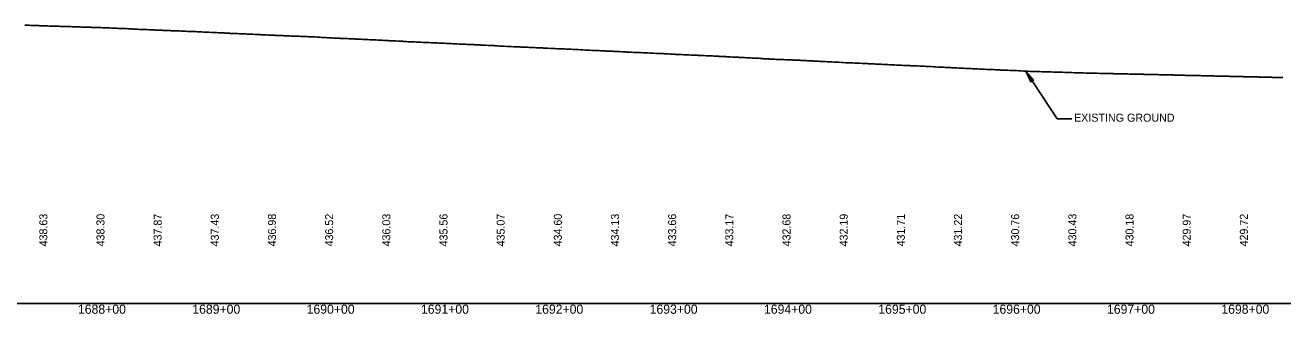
# Model space of a CAD drawing. Extents: x 2017200 to 2047700, y 854850 to 893350.
# Drawn here: x 2023730 to 2024830, y 856091 to 856344 of the extents above; entities that cross this region are included whole.
import ezdxf

# ---------------------------------------------------------------- set-up
doc = ezdxf.new("R2010")
doc.units = 0
for name, color, linetype in [('RD_DDB_Profile_EX', 7, 'Continuous'), ('RD_DDB_Profile_Lbl', 7, 'Continuous'), ('RD_DDB_StaTX', 7, 'Continuous'), ('RD_DDB_StripGrade', 7, 'Continuous'), ('RD_GPK_Profile_Cell', 7, 'Continuous')]:
    doc.layers.add(name, color=color, linetype=linetype)

msp = doc.modelspace()

# ---------------------------------------------------------------- linework, layer by layer
at = {"layer": 'RD_DDB_Profile_EX'}
msp.add_lwpolyline([(2023729.2, 856343.9), (2023729.6, 856343.9), (2023730.4, 856343.9), (2023731.1, 856343.8), (2023732.5, 856343.8), (2023733.1, 856343.8), (2023734.5, 856343.7), (2023735.1, 856343.7), (2023736.6, 856343.6), (2023737.1, 856343.6), (2023737.4, 856343.6), (2023738.7, 856343.6), (2023739, 856343.6), (2023740.7, 856343.5), (2023741.5, 856343.5), (2023742.4, 856343.4), (2023743.4, 856343.4), (2023744.5, 856343.4), (2023745.3, 856343.3), (2023746.7, 856343.3), (2023747.2, 856343.3), (2023748.7, 856343.2), (2023749.2, 856343.2), (2023750.8, 856343.1), (2023751.2, 856343.1), (2023753.2, 856343), (2023755.2, 856343), (2023756.9, 856342.9), (2023757.6, 856342.9), (2023758.7, 856342.9), (2023759.5, 856342.9), (2023760.8, 856342.8), (2023761.4, 856342.8), (2023762.9, 856342.8), (2023763.4, 856342.8), (2023764.9, 856342.7), (2023765.4, 856342.7), (2023767, 856342.6), (2023767.4, 856342.6), (2023768.6, 856342.6), (2023769, 856342.6), (2023769.4, 856342.6), (2023771, 856342.5), (2023772.2, 856342.4), (2023772.6, 856342.4), (2023773.9, 856342.4), (2023774.8, 856342.4), (2023775.8, 856342.3), (2023776.4, 856342.3), (2023776.9, 856342.3), (2023777.7, 856342.3), (2023779, 856342.2), (2023779.6, 856342.2), (2023781.1, 856342.2), (2023781.6, 856342.1), (2023783.1, 856342.1), (2023783.6, 856342.1), (2023784.2, 856342.1), (2023785.2, 856342), (2023785.5, 856342), (2023787.2, 856342), (2023787.5, 856341.9), (2023789.2, 856341.9), (2023790.1, 856341.8), (2023791, 856341.8), (2023792, 856341.8), (2023793.1, 856341.8), (2023793.8, 856341.7), (2023795.2, 856341.7), (2023795.8, 856341.7), (2023797.2, 856341.6), (2023797.7, 856341.6), (2023799.3, 856341.5), (2023799.8, 856341.5), (2023801.3, 856341.5), (2023801.7, 856341.4), (2023803.3, 856341.4), (2023805.1, 856341.3), (2023806.5, 856341.2), (2023807.2, 856341.2), (2023807.6, 856341.2), (2023808.3, 856341.2), (2023809.3, 856341.1), (2023810.2, 856341.1), (2023811.3, 856341), (2023812.1, 856341), (2023813.4, 856341), (2023814, 856340.9), (2023815.4, 856340.9), (2023816, 856340.8), (2023817.5, 856340.8), (2023818, 856340.8), (2023819.5, 856340.7), (2023819.9, 856340.7), (2023821.5, 856340.6), (2023822.8, 856340.6), (2023823.4, 856340.5), (2023824.5, 856340.5), (2023825.5, 856340.4), (2023826.4, 856340.4), (2023827.5, 856340.3), (2023828.3, 856340.3), (2023829.6, 856340.2), (2023830.2, 856340.2), (2023831, 856340.2), (2023831.6, 856340.2), (2023832.1, 856340.1), (2023833.6, 856340), (2023834.1, 856340), (2023835.7, 856340), (2023836.1, 856340), (2023837.7, 856339.9), (2023838.8, 856339.9), (2023839.6, 856339.8), (2023841, 856339.8), (2023841.7, 856339.7), (2023842.8, 856339.7), (2023843.7, 856339.6), (2023844.6, 856339.5), (2023845.7, 856339.5), (2023846.6, 856339.5), (2023847.8, 856339.4), (2023848.5, 856339.4), (2023849.8, 856339.4), (2023850.4, 856339.3), (2023851.8, 856339.3), (2023852.4, 856339.3), (2023853.8, 856339.2), (2023854.4, 856339.2), (2023855.8, 856339.1), (2023856.7, 856339.1), (2023857.5, 856339), (2023857.9, 856339), (2023859.2, 856339), (2023859.9, 856338.9), (2023861, 856338.9), (2023861.9, 856338.8), (2023862.2, 856338.8), (2023862.9, 856338.8), (2023863.9, 856338.8), (2023864.8, 856338.8), (2023866, 856338.7), (2023866.7, 856338.7), (2023868, 856338.6), (2023868.7, 856338.6), (2023870, 856338.5), (2023871.7, 856338.4), (2023872.1, 856338.4), (2023874.1, 856338.3), (2023874.8, 856338.3), (2023876.1, 856338.3), (2023876.4, 856338.3), (2023877.8, 856338.2), (2023878.1, 856338.2), (2023878.8, 856338.2), (2023880.1, 856338.1), (2023881.1, 856338.1), (2023882.2, 856338), (2023883.2, 856337.9), (2023884.2, 856337.9), (2023885.6, 856337.8), (2023886.2, 856337.8), (2023887.5, 856337.7), (2023888.2, 856337.7), (2023889.6, 856337.6), (2023890.2, 856337.6), (2023892.5, 856337.5), (2023893.4, 856337.5), (2023894.4, 856337.4), (2023894.7, 856337.4), (2023896.4, 856337.3), (2023897.1, 856337.3), (2023898.4, 856337.2), (2023899.4, 856337.2), (2023900.4, 856337.1), (2023901.2, 856337.1), (2023901.6, 856337.1), (2023902.4, 856337.1), (2023903.7, 856337), (2023904.4, 856336.9), (2023905.8, 856336.9), (2023906.4, 856336.9), (2023907.9, 856336.8), (2023908.4, 856336.8), (2023909, 856336.7), (2023909.9, 856336.7), (2023910.4, 856336.7), (2023912.8, 856336.6), (2023914.6, 856336.5), (2023915.3, 856336.5), (2023916.8, 856336.4), (2023917.5, 856336.4), (2023918.6, 856336.3), (2023919.7, 856336.3), (2023920.6, 856336.3), (2023921.8, 856336.2), (2023922.6, 856336.2), (2023923.9, 856336.1), (2023924.6, 856336.1), (2023926, 856336), (2023926.6, 856336), (2023928.1, 856335.9), (2023928.6, 856335.9), (2023930.9, 856335.8), (2023931.4, 856335.7), (2023932.4, 856335.7), (2023932.9, 856335.7), (2023933.3, 856335.6), (2023934.8, 856335.6), (2023935.6, 856335.5), (2023936.8, 856335.5), (2023937.8, 856335.4), (2023938.8, 856335.4), (2023940.2, 856335.3), (2023940.8, 856335.3), (2023942.1, 856335.2), (2023942.8, 856335.2), (2023944.2, 856335.1), (2023944.8, 856335.1), (2023946.2, 856335), (2023946.8, 856335), (2023948, 856335), (2023948.3, 856334.9), (2023948.8, 856334.9), (2023950.4, 856334.9), (2023951.2, 856334.9), (2023953.1, 856334.8), (2023953.7, 856334.7), (2023955.1, 856334.7), (2023955.9, 856334.6), (2023957, 856334.6), (2023958.1, 856334.5), (2023959, 856334.5), (2023960.2, 856334.4), (2023961, 856334.4), (2023962.3, 856334.3), (2023963, 856334.3), (2023963.6, 856334.3), (2023964.4, 856334.2), (2023965, 856334.2), (2023966.5, 856334.2), (2023967, 856334.1), (2023968.6, 856334.1), (2023969, 856334.1), (2023970.6, 856334), (2023971.5, 856334), (2023973.4, 856333.9), (2023973.9, 856333.9), (2023975.3, 856333.8), (2023976.2, 856333.8), (2023977.3, 856333.7), (2023978.3, 856333.7), (2023979.3, 856333.6), (2023980.4, 856333.6), (2023981.2, 856333.5), (2023982.5, 856333.5), (2023983.3, 856333.5), (2023984.6, 856333.4), (2023985.3, 856333.3), (2023986.6, 856333.3), (2023987.3, 856333.2), (2023988.7, 856333.1), (2023989.3, 856333.1), (2023990.7, 856333), (2023991.8, 856333), (2023992.3, 856333), (2023993.7, 856332.9), (2023994, 856332.9), (2023994.8, 856332.9), (2023995.6, 856332.8), (2023996.3, 856332.8), (2023997.6, 856332.7), (2023998.4, 856332.7), (2023999.5, 856332.6), (2024000.6, 856332.6), (2024001.5, 856332.5), (2024002.7, 856332.5), (2024003.5, 856332.4), (2024004.8, 856332.4), (2024005.5, 856332.3), (2024006.8, 856332.3), (2024007.5, 856332.2), (2024008.9, 856332.2), (2024009.5, 856332.2), (2024010.4, 856332.1), (2024011, 856332.1), (2024011.5, 856332.1), (2024013, 856332), (2024014.1, 856331.9), (2024015.9, 856331.8), (2024016.5, 856331.8), (2024017.8, 856331.8), (2024018.2, 856331.8), (2024018.7, 856331.7), (2024019.7, 856331.7), (2024020.8, 856331.7), (2024021.7, 856331.6), (2024022.9, 856331.5), (2024023.7, 856331.5), (2024025, 856331.4), (2024025.7, 856331.4), (2024026, 856331.4), (2024027.1, 856331.3), (2024027.7, 856331.3), (2024029.1, 856331.2), (2024029.7, 856331.2), (2024031.2, 856331.1), (2024031.7, 856331.1), (2024033.2, 856331), (2024033.8, 856331), (2024035.2, 856330.9), (2024036.4, 856330.9), (2024038.2, 856330.8), (2024038.7, 856330.7), (2024040.1, 856330.7), (2024040.9, 856330.6), (2024041.6, 856330.6), (2024042, 856330.6), (2024043, 856330.5), (2024044, 856330.4), (2024045.1, 856330.4), (2024045.9, 856330.4), (2024047.2, 856330.3), (2024047.9, 856330.2), (2024049.4, 856330.2), (2024049.9, 856330.2), (2024051.4, 856330.1), (2024051.9, 856330.1), (2024053.4, 856330), (2024053.9, 856330), (2024055.5, 856329.9), (2024055.9, 856329.9), (2024057.2, 856329.8), (2024057.5, 856329.8), (2024057.9, 856329.8), (2024059.5, 856329.7), (2024060.4, 856329.6), (2024061, 856329.6), (2024062.3, 856329.5), (2024063.2, 856329.5), (2024064.2, 856329.4), (2024065, 856329.4), (2024065.3, 856329.4), (2024066.2, 856329.3), (2024067.4, 856329.3), (2024068.2, 856329.3), (2024069.4, 856329.2), (2024070.1, 856329.2), (2024071.5, 856329.1), (2024072.1, 856329.1), (2024072.8, 856329), (2024073.6, 856329), (2024074.1, 856329), (2024075.6, 856328.9), (2024076.1, 856328.9), (2024077.6, 856328.8), (2024078.1, 856328.8), (2024079.7, 856328.7), (2024080.1, 856328.7), (2024080.6, 856328.7), (2024081.7, 856328.6), (2024083, 856328.6), (2024084.7, 856328.5), (2024085.3, 856328.5), (2024086.6, 856328.4), (2024087.5, 856328.4), (2024088.5, 856328.3), (2024089.6, 856328.3), (2024090.4, 856328.3), (2024091.7, 856328.2), (2024092.3, 856328.1), (2024093.8, 856328.1), (2024094.3, 856328), (2024095.8, 856328), (2024096.3, 856328), (2024097.9, 856327.9), (2024098.3, 856327.8), (2024099.9, 856327.8), (2024100.3, 856327.8), (2024101.9, 856327.7), (2024102.3, 856327.7), (2024104, 856327.6), (2024104.4, 856327.6), (2024106, 856327.5), (2024107.3, 856327.4), (2024109, 856327.3), (2024109.5, 856327.3), (2024110.9, 856327.2), (2024111.8, 856327.2), (2024112.8, 856327.2), (2024113.8, 856327.1), (2024114.7, 856327.1), (2024115.9, 856327), (2024116.7, 856327), (2024117.9, 856326.9), (2024118.6, 856326.9), (2024119.6, 856326.9), (2024120, 856326.8), (2024120.6, 856326.8), (2024122.1, 856326.8), (2024122.6, 856326.7), (2024124.1, 856326.7), (2024124.6, 856326.6), (2024126.2, 856326.6), (2024126.6, 856326.5), (2024127.4, 856326.5), (2024128.2, 856326.4), (2024128.6, 856326.4), (2024130.2, 856326.3), (2024130.6, 856326.3), (2024132.6, 856326.2), (2024134.6, 856326.1), (2024135.2, 856326.1), (2024136.3, 856326), (2024136.9, 856326), (2024138.1, 856325.9), (2024138.9, 856325.9), (2024140.2, 856325.9), (2024140.8, 856325.8), (2024142.3, 856325.7), (2024143, 856325.7), (2024144.3, 856325.6), (2024144.7, 856325.6), (2024146.4, 856325.5), (2024146.7, 856325.5), (2024148.4, 856325.4), (2024148.7, 856325.4), (2024150.8, 856325.3), (2024152.7, 856325.2), (2024154.8, 856325.1), (2024156.8, 856325), (2024158.8, 856324.9), (2024160.8, 856324.8), (2024162.6, 856324.8), (2024163.3, 856324.7), (2024164.3, 856324.7), (2024165.2, 856324.6), (2024166.4, 856324.6), (2024167.1, 856324.6), (2024168.5, 856324.5), (2024169.1, 856324.5), (2024170.5, 856324.4), (2024171.1, 856324.4), (2024172.6, 856324.3), (2024173.1, 856324.3), (2024174.2, 856324.2), (2024174.6, 856324.2), (2024175.1, 856324.2), (2024176.6, 856324.1), (2024177.1, 856324), (2024178.7, 856324), (2024179, 856324), (2024181, 856323.9), (2024182, 856323.9), (2024183, 856323.8), (2024185, 856323.7), (2024187, 856323.6), (2024189, 856323.5), (2024189.8, 856323.4), (2024191, 856323.4), (2024192.9, 856323.3), (2024193.3, 856323.3), (2024194.8, 856323.2), (2024195.3, 856323.2), (2024196.8, 856323.2), (2024197.6, 856323.1), (2024198.9, 856323.1), (2024199.3, 856323), (2024200.9, 856323), (2024201.3, 856323), (2024202.9, 856322.9), (2024203.3, 856322.8), (2024204.9, 856322.8), (2024205.4, 856322.8), (2024207, 856322.7), (2024207.3, 856322.7), (2024209, 856322.6), (2024209.3, 856322.6), (2024211, 856322.5), (2024211.3, 856322.5), (2024213.3, 856322.4), (2024215.3, 856322.3), (2024217.3, 856322.2), (2024219.3, 856322.1), (2024221.3, 856322), (2024223.3, 856322), (2024225.5, 856321.8), (2024227.3, 856321.7), (2024228.7, 856321.7), (2024229.3, 856321.7), (2024231.3, 856321.6), (2024232.4, 856321.5), (2024233.3, 856321.5), (2024235.4, 856321.4), (2024236.5, 856321.3), (2024237.4, 856321.2), (2024239.4, 856321.1), (2024241.5, 856321), (2024243.5, 856321), (2024244.3, 856320.9), (2024245.5, 856320.9), (2024247.6, 856320.8), (2024249.6, 856320.7), (2024251.6, 856320.6), (2024252.1, 856320.5), (2024253.5, 856320.5), (2024254, 856320.4), (2024255.3, 856320.4), (2024255.9, 856320.3), (2024257.4, 856320.3), (2024257.8, 856320.3), (2024259.4, 856320.2), (2024259.9, 856320.1), (2024261.8, 856320), (2024263.7, 856319.9), (2024265.7, 856319.9), (2024267.7, 856319.8), (2024269.8, 856319.7), (2024271.8, 856319.6), (2024273.8, 856319.5), (2024275.8, 856319.4), (2024277.8, 856319.3), (2024279.9, 856319.2), (2024281.9, 856319.1), (2024283.3, 856319), (2024283.9, 856319), (2024285.7, 856318.9), (2024286.6, 856318.9), (2024287.5, 856318.9), (2024288.5, 856318.8), (2024289.6, 856318.7), (2024290.4, 856318.7), (2024291.1, 856318.7), (2024291.7, 856318.7), (2024292.3, 856318.6), (2024293.7, 856318.5), (2024294.3, 856318.5), (2024295.7, 856318.5), (2024296.3, 856318.4), (2024297.8, 856318.4), (2024298.3, 856318.3), (2024298.9, 856318.3), (2024299.8, 856318.3), (2024300.3, 856318.3), (2024301.8, 856318.2), (2024302.3, 856318.2), (2024303.8, 856318.1), (2024304.3, 856318.1), (2024305.8, 856318), (2024306.3, 856318), (2024306.7, 856318), (2024307.9, 856317.9), (2024308.3, 856317.9), (2024309.9, 856317.8), (2024310.3, 856317.8), (2024311.9, 856317.7), (2024312.3, 856317.7), (2024313.9, 856317.6), (2024314.5, 856317.6), (2024316, 856317.6), (2024316.4, 856317.5), (2024318, 856317.5), (2024318.4, 856317.4), (2024320, 856317.4), (2024321.4, 856317.3), (2024321.8, 856317.3), (2024322.3, 856317.2), (2024323.2, 856317.2), (2024323.8, 856317.2), (2024325.1, 856317.1), (2024325.9, 856317.1), (2024327, 856317), (2024327.9, 856317), (2024328.9, 856317), (2024330.1, 856316.9), (2024330.8, 856316.9), (2024332, 856316.8), (2024332.8, 856316.8), (2024334.1, 856316.7), (2024334.7, 856316.6), (2024336.1, 856316.6), (2024336.7, 856316.5), (2024338.1, 856316.5), (2024338.7, 856316.4), (2024340.2, 856316.3), (2024340.6, 856316.3), (2024342.2, 856316.3), (2024342.6, 856316.2), (2024344.2, 856316.1), (2024344.6, 856316.1), (2024345.7, 856316.1), (2024346.2, 856316), (2024346.6, 856316), (2024348.3, 856315.9), (2024348.6, 856315.9), (2024350.3, 856315.8), (2024350.6, 856315.8), (2024352.3, 856315.7), (2024352.7, 856315.7), (2024353.5, 856315.7), (2024354.3, 856315.6), (2024354.7, 856315.6), (2024356.3, 856315.5), (2024356.7, 856315.5), (2024358.4, 856315.4), (2024358.7, 856315.4), (2024360.4, 856315.3), (2024360.7, 856315.3), (2024361.3, 856315.3), (2024362.4, 856315.2), (2024363.6, 856315.2), (2024364.2, 856315.1), (2024365.4, 856315), (2024366.3, 856315), (2024367.3, 856315), (2024368.3, 856314.9), (2024369.3, 856314.8), (2024370.4, 856314.8), (2024371.2, 856314.8), (2024372.4, 856314.7), (2024373.2, 856314.7), (2024374.4, 856314.6), (2024375.1, 856314.5), (2024376.5, 856314.5), (2024377.1, 856314.4), (2024378.5, 856314.4), (2024379.1, 856314.3), (2024380.5, 856314.3), (2024381.1, 856314.2), (2024382.5, 856314.1), (2024383.1, 856314.1), (2024384.7, 856314), (2024385.1, 856314), (2024386.6, 856313.9), (2024387.1, 856313.9), (2024388.6, 856313.9), (2024389.1, 856313.8), (2024390.6, 856313.7), (2024391.1, 856313.7), (2024392.7, 856313.7), (2024393.1, 856313.7), (2024394.7, 856313.6), (2024395.1, 856313.6), (2024396.7, 856313.5), (2024397.1, 856313.5), (2024398.7, 856313.4), (2024399.1, 856313.4), (2024400.3, 856313.4), (2024400.8, 856313.4), (2024401.1, 856313.3), (2024402.8, 856313.3), (2024403.1, 856313.2), (2024405.1, 856313.2), (2024407.1, 856313.1), (2024408.1, 856313), (2024408.8, 856313), (2024410, 856312.9), (2024410.7, 856312.9), (2024411.9, 856312.9), (2024412.7, 856312.9), (2024413.8, 856312.7), (2024414.8, 856312.7), (2024415.9, 856312.7), (2024416.8, 856312.6), (2024417.7, 856312.6), (2024418.8, 856312.5), (2024419.7, 856312.4), (2024420.9, 856312.3), (2024421.6, 856312.3), (2024422.9, 856312.2), (2024423.7, 856312.2), (2024424.9, 856312.1), (2024425.5, 856312.1), (2024427, 856312), (2024427.5, 856312), (2024429, 856311.9), (2024429.5, 856311.9), (2024431, 856311.8), (2024431.5, 856311.8), (2024433, 856311.7), (2024433.4, 856311.7), (2024435.1, 856311.6), (2024435.4, 856311.6), (2024437.1, 856311.5), (2024437.4, 856311.5), (2024439.4, 856311.4), (2024441.4, 856311.4), (2024443.4, 856311.2), (2024445.4, 856311.2), (2024447.5, 856311), (2024449.5, 856311), (2024451.5, 856310.8), (2024453.5, 856310.8), (2024454.9, 856310.7), (2024455.6, 856310.7), (2024457.3, 856310.6), (2024457.6, 856310.6), (2024459.6, 856310.5), (2024461.6, 856310.4), (2024462.7, 856310.3), (2024463.3, 856310.3), (2024464.5, 856310.2), (2024465.2, 856310.2), (2024466.4, 856310.2), (2024467.3, 856310.1), (2024468.3, 856310.1), (2024469.3, 856310), (2024470.5, 856310), (2024471.3, 856309.9), (2024472.2, 856309.9), (2024473.4, 856309.8), (2024474.2, 856309.8), (2024475.4, 856309.7), (2024476.1, 856309.7), (2024477.4, 856309.6), (2024478.3, 856309.6), (2024479.4, 856309.5), (2024480.1, 856309.5), (2024481.4, 856309.4), (2024482.1, 856309.4), (2024483.5, 856309.3), (2024484.1, 856309.3), (2024485.5, 856309.2), (2024486.1, 856309.2), (2024487.5, 856309.1), (2024488.1, 856309.1), (2024489.5, 856309), (2024490.1, 856309), (2024491.6, 856308.9), (2024492.1, 856308.9), (2024493.6, 856308.8), (2024494.1, 856308.8), (2024495.6, 856308.8), (2024496, 856308.7), (2024497.6, 856308.6), (2024498, 856308.6), (2024499.7, 856308.6), (2024500, 856308.5), (2024501.7, 856308.4), (2024502, 856308.4), (2024503.7, 856308.4), (2024504, 856308.3), (2024505.7, 856308.3), (2024506, 856308.2), (2024507.7, 856308.2), (2024508, 856308.2), (2024510, 856308.1), (2024512, 856307.9), (2024514.1, 856307.9), (2024516.1, 856307.8), (2024517.3, 856307.7), (2024518.1, 856307.7), (2024520.1, 856307.6), (2024522.1, 856307.5), (2024524.1, 856307.4), (2024525.1, 856307.3), (2024526.1, 856307.3), (2024528.1, 856307.2), (2024530.1, 856307.1), (2024532.2, 856307.1), (2024532.9, 856307), (2024534.2, 856306.9), (2024536, 856306.8), (2024536.8, 856306.8), (2024537.9, 856306.7), (2024538.8, 856306.7), (2024540, 856306.6), (2024540.7, 856306.6), (2024542, 856306.5), (2024542.6, 856306.5), (2024544, 856306.4), (2024544.6, 856306.4), (2024546.1, 856306.3), (2024546.5, 856306.3), (2024548.1, 856306.2), (2024548.5, 856306.2), (2024550.1, 856306.1), (2024550.4, 856306.1), (2024552.1, 856306), (2024552.5, 856306), (2024554.1, 856305.9), (2024554.5, 856305.9), (2024556.6, 856305.8), (2024558.2, 856305.7), (2024558.6, 856305.7), (2024560.2, 856305.6), (2024560.6, 856305.6), (2024562.2, 856305.5), (2024562.6, 856305.5), (2024564.3, 856305.4), (2024564.6, 856305.4), (2024566.5, 856305.3), (2024568.5, 856305.2), (2024570.5, 856305.1), (2024571.9, 856305), (2024572.6, 856305), (2024574.6, 856304.9), (2024576.7, 856304.9), (2024578.4, 856304.7), (2024578.7, 856304.7), (2024579.7, 856304.7), (2024580.4, 856304.7), (2024580.7, 856304.7), (2024582.4, 856304.6), (2024582.7, 856304.5), (2024584.4, 856304.5), (2024584.7, 856304.5), (2024586.4, 856304.4), (2024586.8, 856304.3), (2024587.5, 856304.3), (2024588.5, 856304.3), (2024588.8, 856304.3), (2024590.8, 856304.2), (2024592.8, 856304.1), (2024594.8, 856304), (2024595.3, 856304), (2024596.8, 856304), (2024598.8, 856303.9), (2024600.8, 856303.8), (2024602.8, 856303.7), (2024603.1, 856303.7), (2024604.8, 856303.6), (2024606.8, 856303.5), (2024608.8, 856303.4), (2024610.9, 856303.4), (2024612.8, 856303.3), (2024614.8, 856303.3), (2024616.8, 856303.2), (2024618.8, 856303.1), (2024620.9, 856303.1), (2024622.9, 856303), (2024624.9, 856302.9), (2024626.5, 856302.9), (2024626.9, 856302.9), (2024629, 856302.8), (2024631, 856302.8), (2024633, 856302.7), (2024634.3, 856302.7), (2024635, 856302.6), (2024637, 856302.6), (2024639, 856302.5), (2024641.1, 856302.4), (2024642.1, 856302.4), (2024643, 856302.4), (2024645, 856302.3), (2024647, 856302.2), (2024648.1, 856302.2), (2024649.1, 856302.2), (2024649.9, 856302.1), (2024651.3, 856302.1), (2024653.1, 856302.1), (2024655.2, 856302), (2024657.2, 856301.9), (2024657.7, 856301.9), (2024659.2, 856301.9), (2024661.3, 856301.8), (2024663.3, 856301.8), (2024665.5, 856301.7), (2024667.3, 856301.7), (2024669.4, 856301.6), (2024671.4, 856301.6), (2024673.4, 856301.5), (2024675.3, 856301.5), (2024675.8, 856301.5), (2024677.2, 856301.5), (2024677.8, 856301.4), (2024679.3, 856301.4), (2024679.8, 856301.4), (2024681.3, 856301.4), (2024681.9, 856301.3), (2024683.3, 856301.3), (2024683.9, 856301.3), (2024685.3, 856301.3), (2024685.9, 856301.2), (2024687.3, 856301.2), (2024687.9, 856301.2), (2024688.9, 856301.2), (2024689.4, 856301.2), (2024689.9, 856301.1), (2024691.4, 856301.1), (2024692, 856301.1), (2024693.4, 856301.1), (2024694, 856301.1), (2024695.4, 856301), (2024696, 856301), (2024696.7, 856301), (2024697.4, 856301), (2024698.1, 856301), (2024699.4, 856300.9), (2024700.1, 856300.9), (2024701.5, 856300.9), (2024702.2, 856300.9), (2024703.5, 856300.9), (2024704.5, 856300.8), (2024705.5, 856300.8), (2024706.2, 856300.8), (2024707.5, 856300.8), (2024708.3, 856300.7), (2024709.5, 856300.7), (2024710.3, 856300.7), (2024711.5, 856300.7), (2024712.3, 856300.7), (2024713.5, 856300.6), (2024714.4, 856300.6), (2024715.6, 856300.6), (2024716.4, 856300.6), (2024717.6, 856300.5), (2024718.4, 856300.5), (2024719.6, 856300.5), (2024720.1, 856300.5), (2024720.5, 856300.5), (2024721.6, 856300.4), (2024722.5, 856300.4), (2024723.6, 856300.4), (2024724.5, 856300.4), (2024725.6, 856300.3), (2024726.5, 856300.3), (2024727.6, 856300.3), (2024728.5, 856300.3), (2024729.6, 856300.3), (2024730.5, 856300.2), (2024731.6, 856300.2), (2024732.6, 856300.2), (2024733.6, 856300.2), (2024734.6, 856300.1), (2024735.6, 856300.1), (2024736.6, 856300.1), (2024737.6, 856300.1), (2024738.6, 856300.1), (2024739.6, 856300), (2024740.6, 856300), (2024741.6, 856300), (2024742.6, 856300), (2024743.6, 856300), (2024744.6, 856299.9), (2024745.6, 856299.9), (2024746.6, 856299.9), (2024747.6, 856299.9), (2024748.6, 856299.9), (2024749.6, 856299.8), (2024750.7, 856299.8), (2024751.6, 856299.8), (2024752.7, 856299.8), (2024753.6, 856299.7), (2024754.7, 856299.7), (2024755.6, 856299.7), (2024756.7, 856299.7), (2024757.6, 856299.7), (2024758.7, 856299.6), (2024759.6, 856299.6), (2024760.7, 856299.6), (2024761.6, 856299.6), (2024762.7, 856299.5), (2024763.6, 856299.5), (2024764.6, 856299.5), (2024765.6, 856299.4), (2024766.6, 856299.4), (2024767.6, 856299.4), (2024768.6, 856299.4), (2024769.6, 856299.4), (2024770.6, 856299.3), (2024771.6, 856299.3), (2024772.6, 856299.3), (2024773.6, 856299.3), (2024774.6, 856299.3), (2024775.6, 856299.2), (2024776.6, 856299.2), (2024777.6, 856299.2), (2024778.6, 856299.2), (2024779.6, 856299.1), (2024780.6, 856299.1), (2024781.6, 856299.1), (2024782.6, 856299.1), (2024783.6, 856299), (2024784.6, 856299), (2024785.6, 856299), (2024786.6, 856299), (2024787.6, 856298.9), (2024788.6, 856298.9), (2024789.6, 856298.9), (2024790.6, 856298.9), (2024791.6, 856298.8), (2024792.6, 856298.8), (2024793.6, 856298.8), (2024794.6, 856298.8), (2024795.6, 856298.7), (2024796.6, 856298.7), (2024797.6, 856298.7), (2024798.6, 856298.7), (2024799.6, 856298.6), (2024800.6, 856298.6), (2024801.6, 856298.6), (2024802.6, 856298.6), (2024803.6, 856298.5), (2024804.6, 856298.5), (2024805.6, 856298.5), (2024806.6, 856298.5), (2024807.6, 856298.5), (2024808.6, 856298.4), (2024809.6, 856298.4), (2024810.6, 856298.4), (2024811.6, 856298.4), (2024812.6, 856298.3), (2024813.6, 856298.3), (2024814.6, 856298.3), (2024815.6, 856298.3), (2024816.6, 856298.2), (2024817.6, 856298.2), (2024818.6, 856298.2), (2024819.6, 856298.2), (2024820.5, 856298.1), (2024821.6, 856298.1), (2024822.5, 856298.1), (2024823.6, 856298.1), (2024824.5, 856298), (2024825.6, 856298), (2024826.5, 856298), (2024827.6, 856298), (2024828.5, 856297.9), (2024829.6, 856297.9)], dxfattribs=at)
at = {"layer": 'RD_DDB_Profile_Lbl'}
for p, q in [((2024632.2, 856261.9), (2024604.8, 856303.6)), ((2024645.1, 856261.9), (2024632.2, 856261.9))]:
    msp.add_line(p, q, dxfattribs=at)
msp.add_lwpolyline([(2024604.8, 856303.6), (2024609.2, 856294.1), (2024609.6, 856296.3), (2024611.7, 856295.8)], close=True, dxfattribs=at)
at = {"layer": 'RD_GPK_Profile_Cell'}
msp.add_line((2020500, 856100), (2047700, 856100), dxfattribs=at)

# ---------------------------------------------------------------- texts
at = {"layer": 'RD_DDB_Profile_Lbl'}
msp.add_text('EXISTING GROUND', height=7, dxfattribs=at).set_placement((2024647, 856259.3))
at = {"layer": 'RD_DDB_StaTX'}
for s, p in [('1688+00', (2023775.8, 856091)), ('1689+00', (2023875.8, 856091)), ('1690+00', (2023975.8, 856091)), ('1691+00', (2024075.8, 856091)), ('1692+00', (2024175.8, 856091)), ('1693+00', (2024275.8, 856091)), ('1694+00', (2024375.8, 856091)), ('1695+00', (2024475.8, 856091)), ('1696+00', (2024575.8, 856091)), ('1697+00', (2024675.8, 856091)), ('1698+00', (2024775.8, 856091))]:
    msp.add_text(s, height=8, dxfattribs=at).set_placement(p)
at = {"layer": 'RD_DDB_StripGrade'}
for s, p in [('438.63', (2023749, 856150)), ('438.30', (2023799, 856150)), ('437.87', (2023849, 856150)), ('437.43', (2023899, 856150)), ('436.98', (2023949, 856150)), ('436.52', (2023999, 856150)), ('436.03', (2024049, 856150)), ('435.56', (2024099, 856150)), ('435.07', (2024149, 856150)), ('434.60', (2024199, 856150)), ('434.13', (2024249, 856150)), ('433.66', (2024299, 856150)), ('433.17', (2024349, 856150)), ('432.68', (2024399, 856150)), ('432.19', (2024449, 856150)), ('431.71', (2024499, 856150)), ('431.22', (2024549, 856150)), ('430.76', (2024599, 856150)), ('430.43', (2024649, 856150)), ('430.18', (2024699, 856150)), ('429.97', (2024749, 856150)), ('429.72', (2024799, 856150))]:
    msp.add_text(s, height=7, rotation=90, dxfattribs=at).set_placement(p)

doc.saveas('drawing.dxf')
